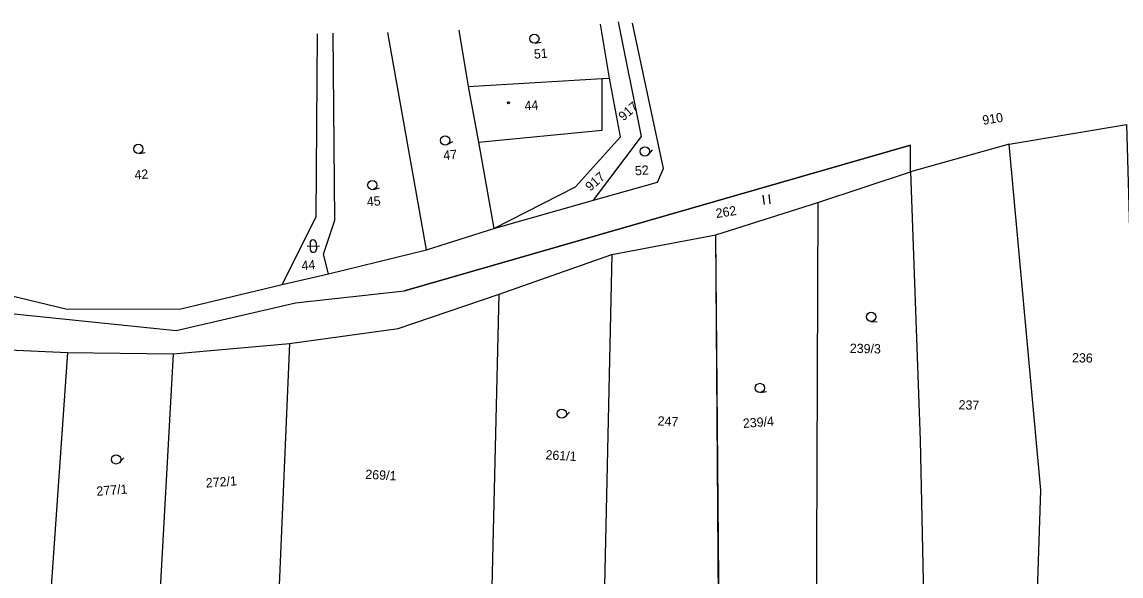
# Model space of a CAD drawing. Extents: x -514509 to -512782, y -1144610 to -1143439.
# Drawn here: x -513195.4 to -513017.7, y -1143555.3 to -1143465.7 of the extents above; entities that cross this region are included whole.
import ezdxf

# ---------------------------------------------------------------- set-up
doc = ezdxf.new("R2010")
doc.units = 0
doc.layers.add('Vrstva 8', color=7, linetype='Continuous')
doc.layers.add('Vrstva 9', color=7, linetype='Continuous')

msp = doc.modelspace()

# ---------------------------------------------------------------- linework, layer by layer
at = {"layer": 'Vrstva 8'}
for p, q in [((-513129.991, -1143502.537), (-513136.246, -1143467.378)), ((-513101.596, -1143483.176), (-513101.558, -1143474.84)), ((-513121.563, -1143485.108), (-513101.596, -1143483.176)), ((-513082.649, -1143574.448), (-513083.213, -1143500.109)), ((-513100.018, -1143503.277), (-513101.529, -1143571.795)), ((-513119.665, -1143569.25), (-513118.241, -1143509.714)), ((-513152.121, -1143517.671), (-513154.1, -1143564.42)), ((-513188.029, -1143519.148), (-513191.434, -1143567.629)), ((-513170.934, -1143519.353), (-513173.531, -1143566.091))]:
    msp.add_line(p, q, dxfattribs=at)
for points in [[(-513145.834, -1143506.437), (-513129.991, -1143502.537), (-513119.072, -1143499.082), (-513103.001, -1143494.493), (-513092.649, -1143491.608), (-513091.691, -1143489.388), (-513096.67, -1143465.876)], [(-513124.78, -1143466.989), (-513123.218, -1143476.089), (-513121.563, -1143485.108), (-513119.072, -1143499.082), (-513105.891, -1143492.371), (-513098.623, -1143484.241), (-513100.417, -1143474.765), (-513101.833, -1143466.033)], [(-513103.001, -1143494.493), (-513095.215, -1143484.192), (-513098.924, -1143465.673)], [(-513270.619, -1143495.675), (-513257.778, -1143497.804), (-513252.852, -1143499.577), (-513242.853, -1143502.338), (-513234.38, -1143504.518), (-513203.52, -1143508.443), (-513188.094, -1143512.134), (-513169.671, -1143512.103), (-513153.301, -1143508.162), (-513147.822, -1143497.21), (-513147.612, -1143467.6)], [(-513153.301, -1143508.162), (-513145.834, -1143506.437), (-513146.634, -1143503.26), (-513144.808, -1143497.747), (-513145.071, -1143467.473)], [(-513123.218, -1143476.089), (-513101.558, -1143474.84), (-513100.417, -1143474.765)], [(-513035.778, -1143485.469), (-513016.814, -1143482.262), (-513013.645, -1143592.585)], [(-513242.174, -1143505.947), (-513212.991, -1143511.229), (-513170.466, -1143515.58), (-513151.173, -1143511.103), (-513133.554, -1143509.18), (-513051.737, -1143485.623)], [(-513032.15, -1143587.352), (-513030.67, -1143541.436), (-513035.778, -1143485.469), (-513051.738, -1143489.896), (-513051.737, -1143485.623), (-513133.554, -1143509.18)], [(-513066.715, -1143494.873), (-513051.738, -1143489.896), (-513050.167, -1143533.331), (-513049.523, -1143563.665), (-513049.36, -1143585.88)], [(-513082.58, -1143574.42), (-513083.213, -1143500.109), (-513066.715, -1143494.873), (-513067.053, -1143579.777)], [(-513243.25, -1143516.407), (-513225.43, -1143517.387), (-513205.862, -1143518.345), (-513188.029, -1143519.148), (-513170.934, -1143519.353), (-513152.121, -1143517.671), (-513134.561, -1143515.256), (-513118.241, -1143509.714), (-513100.018, -1143503.277), (-513083.213, -1143500.109)]]:
    msp.add_lwpolyline(points, dxfattribs=at)
at = {"layer": 'Vrstva 9'}
for p, q in [((-513112.399, -1143469.117), (-513111.418, -1143468.928)), ((-513126.614, -1143485.502), (-513125.729, -1143485.038)), ((-513094.109, -1143487.123), (-513093.442, -1143486.379)), ((-513176.446, -1143486.951), (-513175.46, -1143486.791)), ((-513138.546, -1143492.78), (-513137.583, -1143492.514)), ((-513074.419, -1143495.078), (-513074.584, -1143493.587)), ((-513075.579, -1143493.698), (-513075.413, -1143495.189)), ((-513149.279, -1143501.97), (-513147.28, -1143501.895)), ((-513148.799, -1143501.449), (-513148.762, -1143502.449)), ((-513147.799, -1143501.413), (-513147.763, -1143502.413)), ((-513058.136, -1143514.125), (-513057.139, -1143514.184)), ((-513075.984, -1143525.626), (-513074.995, -1143525.486)), ((-513107.548, -1143529.547), (-513106.881, -1143528.803)), ((-513179.592, -1143536.943), (-513178.925, -1143536.199))]:
    msp.add_line(p, q, dxfattribs=at)
for centre, radius in [((-513112.542, -1143468.38), 0.75), ((-513116.715, -1143478.743), 0.175), ((-513126.962, -1143484.837), 0.75), ((-513176.567, -1143486.211), 0.75), ((-513094.668, -1143486.623), 0.75), ((-513138.746, -1143492.057), 0.75), ((-513058.092, -1143513.376), 0.75), ((-513076.09, -1143524.884), 0.75), ((-513108.107, -1143529.047), 0.75), ((-513180.151, -1143536.443), 0.75)]:
    msp.add_circle(centre, radius, dxfattribs=at)
for centre, start, end in [((-513148.299, -1143501.432), 2.05659, 182.05659), ((-513148.263, -1143502.431), 182.05659, 2.05659)]:
    msp.add_arc(centre, 0.5, start, end, dxfattribs=at)

# ---------------------------------------------------------------- texts
for s, rotation, p in [('51', 4.36014, (-513112.572, -1143471.621)), ('44', 4.36014, (-513114.084, -1143479.984)), ('917', 40.90539, (-513098.147, -1143481.771)), ('910', 8.90824, (-513039.987, -1143482.325)), ('47', 4.36014, (-513127.214, -1143487.991)), ('42', 4.36014, (-513177.13, -1143491.168)), ('917', 40.90539, (-513103.508, -1143493.14)), ('52', 4.36014, (-513096.22, -1143490.504)), ('45', 4.36014, (-513139.568, -1143495.506)), ('262', 8.90824, (-513083.095, -1143497.406)), ('44', 4.36014, (-513150.143, -1143505.829)), ('239/3', 358.77667, (-513061.556, -1143519.204)), ('236', 358.8715, (-513025.63, -1143520.737)), ('237', 358.42526, (-513043.974, -1143528.349)), ('247', 356.83548, (-513092.649, -1143530.938)), ('239/4', 4.36014, (-513078.771, -1143531.367)), ('261/1', 356.83548, (-513110.773, -1143536.43)), ('269/1', 356.83548, (-513139.901, -1143539.583)), ('272/1', 4.36014, (-513165.595, -1143541.017)), ('277/1', 4.36014, (-513183.286, -1143542.344))]:
    msp.add_text(s, height=1.5, rotation=rotation, dxfattribs=at).set_placement(p)

doc.saveas('drawing.dxf')
